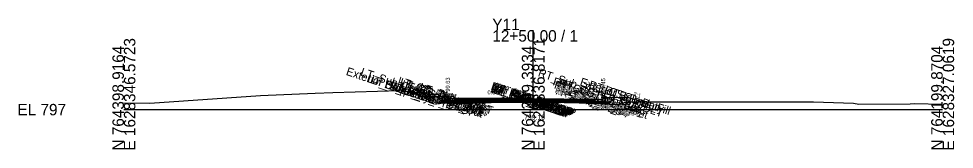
# Model space of a CAD drawing. Extents: x -26 to 203, y -10 to 6017.
# Drawn here: x -25.7 to 202.8, y 4990.3 to 5022.2 of the extents above; entities that cross this region are included whole.
import ezdxf

# ---------------------------------------------------------------- set-up
doc = ezdxf.new("R2010")
doc.units = 0
for name, color, linetype in [('Default', 7, 'Continuous'), ('Exist Cross Section Cell', 7, 'Continuous'), ('Exist XS Center Line Elevation Label', 7, 'Continuous'), ('Exist XS Ground Line', 7, 'Continuous'), ('Prop CMT Conc Surface', 7, 'Continuous'), ('Prop CMT Concrete Structures', 7, 'Continuous'), ('Prop CMT Pvmt Course 1', 7, 'Continuous'), ('Prop CMT Pvmt Course 1 CG', 7, 'Continuous'), ('Prop CMT Pvmt Course 2', 7, 'Continuous'), ('Prop CMT Pvmt Course 3', 7, 'Continuous'), ('Prop CMT Pvmt Surface', 7, 'Continuous'), ('Prop CMT Pvmt Wedge Surface 1', 7, 'Continuous'), ('Prop CMT Pvmt Wedge Surface 2', 7, 'Continuous'), ('Prop CMT Pvmt Wedge Surface 3', 7, 'Continuous'), ('Prop CMT Slope Grass', 7, 'Continuous'), ('Prop CMT Subgrade Earthwork', 7, 'Continuous'), ('Prop XS Hydro Elevations', 7, 'Continuous'), ('Prop XS SE Text', 7, 'Continuous'), ('Prop XS Side Slope Text', 7, 'Continuous'), ('Scratch_Level_0', 7, 'Continuous')]:
    doc.layers.add(name, color=color, linetype=linetype)

msp = doc.modelspace()

# ---------------------------------------------------------------- linework, layer by layer
at = {"layer": 'Exist Cross Section Cell'}
for p, q in [((100, 5000), (100, 5019.41)), ((0, 5000), (100, 5000)), ((100, 5000), (200, 5000))]:
    msp.add_line(p, q, dxfattribs=at)
at = {"layer": 'Exist XS Ground Line'}
msp.add_lwpolyline([(0, 5001.62), (6.33, 5001.54), (33.37, 5003.42), (46.74, 5004.02), (51.04, 5004.22), (67.41, 5004.68), (75.82, 5003.73), (76.66, 5003.77), (77.71, 5003.1), (79.13, 5002.15), (79.67, 5001.63), (80.36, 5001.58), (82.26, 5001.47), (88.44, 5001.68), (97.64, 5002.23), (100, 5002.13), (120.58, 5001.27), (121.17, 5001.25), (122.57, 5001.88), (122.96, 5001.77), (123.92, 5001.87), (130.04, 5001.93), (148.36, 5001.92), (151.3, 5001.9), (168.48, 5001.89), (178.26, 5001.55), (179.52, 5001.36), (192.06, 5001.45), (193.04, 5001.49), (200, 5001.36)], dxfattribs=at)
at = {"layer": 'Prop CMT Conc Surface'}
for points in [[(79.12, 5002.63), (79.12, 5003.13), (78.62, 5003.13)], [(81.12, 5002.71), (79.12, 5002.63)], [(117.07, 5002.45), (117.07, 5002.95), (117.57, 5002.95)], [(115.07, 5002.55), (117.07, 5002.45)]]:
    msp.add_lwpolyline(points, dxfattribs=at)
at = {"layer": 'Prop CMT Concrete Structures'}
for points in [[(81.12, 5002.71), (79.12, 5002.63), (79.12, 5003.13), (78.62, 5003.13)], [(78.62, 5003.13), (78.62, 5002.12), (81.12, 5002.12)], [(81.12, 5002.12), (81.12, 5002.71)], [(115.07, 5002.55), (117.07, 5002.45), (117.07, 5002.95), (117.57, 5002.95)], [(117.57, 5002.95), (117.57, 5001.95), (115.07, 5001.97)], [(115.07, 5001.97), (115.07, 5002.55)]]:
    msp.add_lwpolyline(points, dxfattribs=at)
at = {"layer": 'Prop CMT Pvmt Course 1'}
for points in [[(100, 5002.71), (81.12, 5002.71)], [(81.12, 5002.71), (81.12, 5002.45)], [(100, 5002.45), (100, 5002.71)], [(100, 5002.71), (115.07, 5002.55)], [(100, 5002.45), (100, 5002.71)], [(81.12, 5002.45), (100, 5002.45)], [(115.07, 5002.3), (100, 5002.45)], [(115.07, 5002.55), (115.07, 5002.3)]]:
    msp.add_lwpolyline(points, dxfattribs=at)
msp.add_lwpolyline([(100, 5002.45), (100, 5002.58), (100, 5002.58), (100, 5002.45)], close=True, dxfattribs=at)
msp.add_lwpolyline([(100, 5002.45), (100, 5002.58), (100, 5002.58), (100, 5002.45)], close=True, dxfattribs=at)
at = {"layer": 'Prop CMT Pvmt Course 1 CG'}
for points in [[(81.12, 5002.12), (78.12, 5002.12), (77.78, 5001.79)], [(77.78, 5001.79), (81.12, 5001.79)], [(81.12, 5001.79), (81.12, 5002.12)], [(115.07, 5001.97), (118.07, 5001.94), (118.41, 5001.6)], [(115.07, 5001.64), (115.07, 5001.97)], [(118.41, 5001.6), (115.07, 5001.64)]]:
    msp.add_lwpolyline(points, dxfattribs=at)
at = {"layer": 'Prop CMT Pvmt Course 2'}
for points in [[(100, 5002.45), (81.12, 5002.45)], [(81.12, 5002.45), (81.12, 5002.12)], [(81.12, 5002.12), (100, 5002.12)], [(100, 5002.12), (100, 5002.45)], [(100, 5002.12), (100, 5002.45)], [(100, 5002.45), (115.07, 5002.3)], [(100, 5002.45), (100, 5002.45)], [(100, 5002.45), (100, 5002.45)], [(115.07, 5001.97), (100, 5002.12)], [(115.07, 5002.3), (115.07, 5001.97)]]:
    msp.add_lwpolyline(points, dxfattribs=at)
msp.add_lwpolyline([(100, 5002.45), (100, 5002.12), (100, 5002.12)], close=True, dxfattribs=at)
msp.add_lwpolyline([(100, 5002.45), (100, 5002.12), (100, 5002.12)], close=True, dxfattribs=at)
at = {"layer": 'Prop CMT Pvmt Course 3'}
for points in [[(100, 5002.12), (81.12, 5002.12)], [(81.12, 5002.12), (81.12, 5001.79)], [(81.12, 5001.79), (100, 5001.79)], [(100, 5001.79), (100, 5002.12)], [(100, 5002.12), (115.07, 5001.97)], [(100, 5001.79), (100, 5002.12)], [(100, 5002.12), (100, 5002.12), (100, 5001.79), (100, 5001.79)], [(100, 5001.79), (100, 5002.12)], [(100, 5002.12), (100, 5002.12), (100, 5001.79), (100, 5001.79)], [(100, 5001.79), (100, 5002.12)], [(115.07, 5001.64), (100, 5001.79)], [(115.07, 5001.97), (115.07, 5001.64)]]:
    msp.add_lwpolyline(points, dxfattribs=at)
at = {"layer": 'Prop CMT Pvmt Surface'}
for points in [[(100, 5002.71), (81.12, 5002.71)], [(100, 5002.71), (115.07, 5002.55)]]:
    msp.add_lwpolyline(points, dxfattribs=at)
at = {"layer": 'Prop CMT Pvmt Wedge Surface 1'}
for points in [[(100, 5002.71), (100, 5002.45), (100, 5002.45)], [(100, 5002.71), (100, 5002.45), (100, 5002.45)], [(100, 5002.45), (100, 5002.58)], [(100, 5002.45), (100, 5002.58)]]:
    msp.add_lwpolyline(points, dxfattribs=at)
at = {"layer": 'Prop CMT Pvmt Wedge Surface 2'}
for points in [[(100, 5002.71), (100, 5002.45)], [(100, 5002.71), (100, 5002.45)], [(100, 5002.45), (100, 5002.45)], [(100, 5002.45), (100, 5002.45)]]:
    msp.add_lwpolyline(points, dxfattribs=at)
at = {"layer": 'Prop CMT Pvmt Wedge Surface 3'}
for points in [[(100, 5002.71), (100, 5002.12)], [(100, 5002.71), (100, 5002.12)], [(100, 5002.12), (100, 5002.12)], [(100, 5002.12), (100, 5002.12)]]:
    msp.add_lwpolyline(points, dxfattribs=at)
at = {"layer": 'Prop CMT Slope Grass'}
for points in [[(78.62, 5003.13), (73.12, 5003.24), (69.47, 5004.45)], [(117.57, 5002.95), (123.07, 5003.06), (126.59, 5001.89)]]:
    msp.add_lwpolyline(points, dxfattribs=at)
at = {"layer": 'Prop CMT Subgrade Earthwork'}
for points in [[(81.12, 5001.79), (77.78, 5001.79), (76.4, 5003.17)], [(115.07, 5001.64), (118.41, 5001.6), (119.8, 5003)], [(100, 5001.79), (81.12, 5001.79)], [(100, 5001.79), (115.07, 5001.64)]]:
    msp.add_lwpolyline(points, dxfattribs=at)

# ---------------------------------------------------------------- texts
at = {"layer": 'Default'}
msp.add_text('-', height=0.0001, dxfattribs=at).set_placement((0, 5000))
at = {"layer": 'Exist Cross Section Cell'}
for s, p in [('Y11', (90, 5019.41)), ('12+50.00 / 1', (90, 5016.61)), ('EL 797', (-26, 4998.6))]:
    msp.add_text(s, height=2.8, dxfattribs=at).set_placement(p)
for s, p in [('E 1628346.5723', (2.8, 4990)), ('E 1628336.8171', (102.8, 4990)), ('E 1628327.0619', (202.8, 4990)), ('N 764398.9164', (0, 4990)), ('N 764299.3934', (100, 4990)), ('N 764199.8704', (200, 4990))]:
    msp.add_text(s, height=2.8, rotation=90, dxfattribs=at).set_placement(p)
at = {"layer": 'Exist XS Center Line Elevation Label'}
msp.add_text('799.16', height=1.2, dxfattribs=at).set_placement((97.78, 4997.56))
at = {"layer": 'Prop XS Hydro Elevations'}
for s, p in [('799.63', (79.62, 5003.63)), ('799.45', (117.57, 5003.45))]:
    msp.add_text(s, height=1, rotation=90, dxfattribs=at).set_placement(p)
at = {"layer": 'Prop XS SE Text'}
for s, rotation, p in [('0.000', 360, (88.81, 5003.71)), ('0.010', 359.4271, (105.92, 5003.65))]:
    msp.add_text(s, height=1, rotation=rotation, dxfattribs=at).set_placement(p)
at = {"layer": 'Prop XS Side Slope Text'}
for p in [(70.78, 5004.8), (70.78, 5004.8), (124.31, 5003.44)]:
    msp.add_text('3:1', height=1, rotation=341.5668, dxfattribs=at).set_placement(p)
at = {"layer": 'Scratch_Level_0'}
for s, p in [('Exterior Boundary', (54.11, 5008.52)), ('LT_Sub_Trench_Out_DLT', (57.65, 5008.37)), ('RT_Sub_Trench_Out_DLT', (101.01, 5008.21)), ('LT_Slope_Cut', (59.33, 5006.78)), ('LT_Slope_Fill', (60.16, 5006.5)), ('LT_CSLP_Pnt', (63.48, 5005.39)), ('LT_CG1_Shelf_Out', (65.04, 5005.43)), ('LT_CG_Top_Face', (66.71, 5006.21)), ('LT_CG_Top_BOC', (67.18, 5005.88)), ('LT_CG_Top_Gut', (67.64, 5005.4)), ('RT_CG_Top_Face', (104.62, 5006.05)), ('RT_CG_Top_BOC', (106.1, 5005.73)), ('Exterior Boundary', (111.23, 5005.96)), ('LT_CG_Bot_BOC', (67.21, 5004.87)), ('LT_Sub_OEOP', (68.08, 5003.97)), ('LT_CG_Bot_IE', (71.23, 5004.36)), ('LT_Sub_OEOT', (71.39, 5003.98)), ('LT_PV2_OEOT', (71.48, 5004.61)), ('LT_PV3_OEOT', (71.48, 5004.28)), ('LT_PV1_OEOT', (72.02, 5004.68)), ('RT_Sub_OEEOP', (89.41, 5004.27)), ('LT_Sub_OEEOP', (89.45, 5004.25)), ('RT_PV2_OEEOP', (89.49, 5004.9)), ('RT_PV3_OEEOP', (89.49, 5004.57)), ('LT_PV2_OEEOP', (89.54, 5004.89)), ('LT_PV3_OEEOP', (89.54, 5004.55)), ('RT_Sub_IEEOP', (90.02, 5004.06)), ('RT_PV1_OEEOP', (90.03, 5004.85)), ('LT_Sub_IEEOP', (90.06, 5004.05)), ('LT_PV1_OEEOP', (90.08, 5004.83)), ('RT_PV2_IEEOP', (90.11, 5004.7)), ('RT_PV3_IEEOP', (90.11, 5004.37)), ('LT_PV2_IEEOP', (90.15, 5004.68)), ('LT_PV3_IEEOP', (90.15, 5004.35)), ('RT_PV1_IEEOP', (90.65, 5004.64)), ('LT_PV1_IEEOP', (90.69, 5004.63)), ('PV2_PGL', (93.9, 5003.43)), ('PV3_PGL', (93.9, 5003.1)), ('PV1_PGL', (94.44, 5003.5)), ('RT_CG1_Shelf_Out', (104.95, 5005.26)), ('RT_CG_Bot_IE', (105.14, 5004.23)), ('RT_Sub_OEOT', (105.3, 5003.84)), ('RT_PV2_OEOT', (105.39, 5004.48)), ('RT_PV3_OEOT', (105.39, 5004.14)), ('RT_CG_Top_Gut', (105.55, 5005.24)), ('RT_PV1_OEOT', (105.93, 5004.55)), ('RT_CG_Bot_BOC', (106.12, 5004.71)), ('RT_Sub_OEOP', (108.66, 5003.8)), ('RT_CSLP_Pnt', (113.39, 5005.24)), ('RT_Slope_Fill', (117.23, 5003.96)), ('Sub_PGL', (93.81, 5002.8))]:
    msp.add_text(s, height=2, rotation=341.5651, dxfattribs=at).set_placement(p)

doc.saveas('drawing.dxf')
